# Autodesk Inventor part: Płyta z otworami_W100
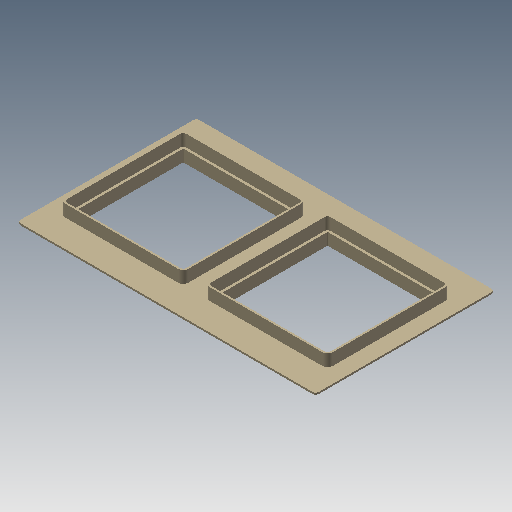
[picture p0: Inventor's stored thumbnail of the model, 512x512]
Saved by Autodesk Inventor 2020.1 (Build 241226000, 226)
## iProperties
Created: 2005-10
Part Number: Płyta z otworami_W100
Document SubType Name: Modeling
Designer: F.Stasiak
Density: 1 g/cm^3
Material: Ogólny
Appearance: Beżowa
Manager: www.cadconsulting.pl
Company: Fabian Stasiak CAD Consulting
Author: F.Stasiak
Subject: Zbiór ćwiczeń. Autodesk Inventor 2020. Kurs podstawowy
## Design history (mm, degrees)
sketch "Szkic2"
  geometry: L1 (250, 150)-(-250, 150); L2 (-250, 150)-(-250, -150); L3 (-250, -150)-(250, -150); L4 (250, -150)-(250, 150); L5 (0, 150)-(0, -150); 2 further points
  constraints: 10 end point, 3 midpoint, 2 parallel, 1 coincident, 1 horizontal, 1 perpendicular
  dimensions: "d0" = 500 distance of L2.end L3.end; "d1" = 300 distance of L1.end L2.end
extrude "Wyciągnięcie proste1" new body sketch "Szkic2" distance "d2" = 20; taper "d3" = 0 deg
sketch "Szkic3"
  geometry: L1 (-217, 97)-(-25, 97); L2 (-25, 97)-(-25, -95); L3 (-25, -95)-(-217, -95); L4 (-217, -95)-(-217, 97); L5 (25, 97)-(217, 97); L6 (217, 97)-(217, -95); L7 (217, -95)-(25, -95); L8 (25, -95)-(25, 97); L9 (-250, 150)-(250, 150) reference; L10 (-250, -150)-(-250, 150) reference; L11 (250, -150)-(-250, -150) reference; L12 (250, 150)-(250, -150) reference
  constraints: 16 end point, 4 parallel, 2 collinear, 2 horizontal, 2 perpendicular
  dimensions: "d4" = 192 distance of L2.end L3.end; "d5" = 192 distance of L6.end L7.end (= d4); "d6" = 50 distance between parallel lines of L8 L2; "d7" = 33 distance between parallel lines of L12 L6; "d8" = 192 distance of L5.end L6.end; "d9" = 53 distance between parallel lines of L9 L5
extrude "Wyciągnięcie proste2" cut sketch "Szkic3" extent not by distance; stored distance "d10" = 20; taper "d11" = 0 deg
fillet "Zaokrąglenie1" dims "d13" = 1
feature "Skorupa1" dims "d12" = 3
fillet "Zaokrąglenie2" dims "d14" = 5
sketch "Szkic4"
  geometry: L1 (-245, 150)-(245, 150) reference; L2 (-250, -145)-(-250, 145) reference; L3 (245, -150)-(-245, -150) reference; L4 (250, 145)-(250, -145) reference; L5 (-217, -96)-(-217, 94) reference; L6 (-216, 95)-(-26, 95) reference; L7 (-25, 94)-(-25, -96) reference; L8 (-26, -97)-(-216, -97) reference; L9 (25, -96)-(25, 94) reference; L10 (26, 95)-(216, 95) reference; L11 (217, 94)-(217, -96) reference; L12 (216, -97)-(26, -97) reference; L13 (-216, -101)-(-26, -101); L14 (-21, -96)-(-21, 94); L15 (-26, 99)-(-216, 99); L16 (-221, 94)-(-221, -96); L17 (26, -101)-(216, -101); L18 (221, -96)-(221, 94); L19 (216, 99)-(26, 99); L20 (21, 94)-(21, -96); L21 (26, 102)-(216, 102); L22 (224, 94)-(224, -96); L23 (216, -104)-(26, -104); L24 (18, -96)-(18, 94); L25 (-216, 102)-(-26, 102); L26 (-18, 94)-(-18, -96); L27 (-26, -104)-(-216, -104); L28 (-224, -96)-(-224, 94); A1 r 5 centre (245, 145) between (250, 145) and (245, 150) reference; A2 r 5 centre (-245, 145) between (-245, 150) and (-250, 145) reference; A3 r 5 centre (-245, -145) between (-250, -145) and (-245, -150) reference; A4 r 5 centre (245, -145) between (245, -150) and (250, -145) reference; A5 r 1 centre (-216, 94) between (-216, 95) and (-217, 94) reference; A6 r 1 centre (-26, 94) between (-25, 94) and (-26, 95) reference; A7 r 1 centre (-26, -96) between (-26, -97) and (-25, -96) reference; A8 r 1 centre (-216, -96) between (-217, -96) and (-216, -97) reference; A9 r 1 centre (26, 94) between (26, 95) and (25, 94) reference; A10 r 1 centre (216, 94) between (217, 94) and (216, 95) reference; A11 r 1 centre (216, -96) between (216, -97) and (217, -96) reference; A12 r 1 centre (26, -96) between (25, -96) and (26, -97) reference; A13 r 5 centre (-26, -96) between (-26, -101) and (-21, -96); A14 r 5 centre (-26, 94) between (-21, 94) and (-26, 99); A15 r 5 centre (-216, 94) between (-216, 99) and (-221, 94); A16 r 5 centre (-216, -96) between (-221, -96) and (-216, -101); A17 r 5 centre (216, -96) between (216, -101) and (221, -96); A18 r 5 centre (216, 94) between (221, 94) and (216, 99); A19 r 5 centre (26, 94) between (26, 99) and (21, 94); A20 r 5 centre (26, -96) between (21, -96) and (26, -101); A21 r 8 centre (216, 94) between (224, 94) and (216, 102); A22 r 8 centre (216, -96) between (216, -104) and (224, -96); A23 r 8 centre (26, -96) between (18, -96) and (26, -104); A24 r 8 centre (26, 94) between (26, 102) and (18, 94); A25 r 8 centre (-26, 94) between (-18, 94) and (-26, 102); A26 r 8 centre (-26, -96) between (-26, -104) and (-18, -96); A27 r 8 centre (-216, -96) between (-224, -96) and (-216, -104); A28 r 8 centre (-216, 94) between (-216, 102) and (-224, 94)
  constraints: 32 end point, 32 point on circle, 16 centre point, 28 other
  dimensions: "d15" = 4 distance between parallel lines of L17 L12; "d16" = 4 distance between parallel lines of L13 L8; "d19" = 3 distance between parallel lines of L25 L15; "d20" = 3 distance between parallel lines of L21 L19
extrude "Wyciągnięcie proste4" join sketch "Szkic4" distance "d21" = 20; taper "d22" = 0 deg
node "Bryła1"
node "Korpusy bryłowe"
node "Korpusy powierzchniowe"
node "Pętla rzutowana1"
node "Pętla rzutowana2"
